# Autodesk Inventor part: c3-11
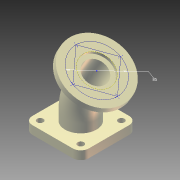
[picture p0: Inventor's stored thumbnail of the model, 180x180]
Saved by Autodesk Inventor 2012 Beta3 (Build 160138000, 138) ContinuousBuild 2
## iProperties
Created: 2010-11
Part Number: c3-11
Material: Cast Iron
Document SubType Name: Modeling
Designer: Beta-8540w
Density: 7.25 g/cm^3
Mass: 1087.5 g
Surface Area: 260 cm^2
Volume: 150 cm^3
Author: Beta-8540w
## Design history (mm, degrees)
sketch "Sketch1"
  geometry: L1 (-50, -50)-(50, -50); L2 (50, -50)-(50, 50); L3 (50, 50)-(-50, 50); L4 (-50, 50)-(-50, -50); C1 r 20 at (0, 0); C2 r 28 at (0, 0); 3 further points
  constraints: 8 end point, 3 perpendicular, 2 centre point, 2 coincident, 2 midpoint, 1 horizontal, 1 horizontal alignment, 1 parallel, 1 vertical alignment
  dimensions: "Width" = 100 distance of L1.start L1.end; "d6" = 40 diameter of C1; "d7" = 8 radial gap between concentric circles of C2 C1
extrude "Extrusion1" new body sketch "Sketch1" distance "d3" = 15; taper "d4" = 0 deg
fillet "Fillet1" dims "d5" = 14
sketch "Sketch2"
  geometry: L1 (0, 0)-(0, 30); L2 (-13.397, 80)-(-28.397, 105.981); A1 r 100 centre (-100, 30) between (0, 30) and (-13.397, 80)
  constraints: 4 end point, 2 point on circle, 2 tangent, 1 centre point, 1 vertical
  dimensions: "d8" = 30 distance of L1.start L1.end; "d9" = 100 radius of A1; "d10" = 30 distance of L2.start L2.end; "d11" = 30 deg angle of L2 L1
sketch "Sketch3"
  geometry: L1 (-13.397, 80)-(-28.397, 105.981) reference; L2 (-28.397, 105.981)-(-76.029, 78.481); L3 (-76.029, 78.481)-(-71.029, 69.821); L4 (-71.029, 69.821)-(-23.397, 97.321); L5 (-23.397, 97.321)-(-28.397, 105.981); 1 further point
  constraints: 8 end point, 2 parallel, 2 perpendicular
  dimensions: "d16" = 10 distance of L3.end L2.end; "d17" = 110 diameter of L3 L5
revolve "Revolution1" sketch "Sketch3" stored, may be unused: angle "d18" = 90 deg
sweep "Sweep1" dims "d19" = 0
sweep "Sweep2" dims "d20" = 0
sketch "Sketch4"
  geometry: C1 r 20 at (0, 0) reference; C2 r 55 at (0, 0) reference; C3 r 27.5 at (0, 0); 1 further point
  constraints: 1 centre point, 1 coincident
  dimensions: "d21" = 55 diameter of C3
extrude "Extrusion2" cut sketch "Sketch4" distance "d22" = 5; taper "d23" = 0 deg
sketch "Sketch5"
  geometry: L1 (0, 0)-(0, 9.711); L2 (-25, 0)-(-27, 0); L3 (-27, 0)-(-27, 1.5); L4 (-26.5, 2)-(-25.5, 2); L5 (-25, 1.5)-(-25, 0); A1 r 0.5 centre (-25.5, 1.5) between (-25, 1.5) and (-25.5, 2); A2 r 0.5 centre (-26.5, 1.5) between (-26.5, 2) and (-27, 1.5); 1 further point
  constraints: 10 end point, 4 point on circle, 4 tangent, 3 point on line, 2 centre point, 2 parallel, 1 equal radius, 1 horizontal, 1 perpendicular, 1 vertical
  dimensions: "d24" = 2 distance of L2.start L2.end; "d25" = 2 distance of point (-25, 2) L2.start; "d26" = 50 diameter of L5 L1; "d27" = 0.5 radius of A1
revolve "Revolution2" sketch "Sketch5" stored, may be unused: angle "d28" = 90 deg
hole "Hole1" diameter "d31" = 11; stored, may be unused: countersink angle "d35" = 7.5 deg, drill point angle "d37" = 118 deg; dims "d29" = 10, "d30" = 10, "d32" = 6, "d33" = 28, "d34" = 2, "d36" = 8
pattern_circular "Circular Pattern1" dims angle "d39" = 360 deg
sketch "Hole Sketch" dims "d41" = 85
  geometry: L1 (0, -42.5)-(-42.5, 0); L2 (-42.5, 0)-(0, 42.5); L3 (0, 42.5)-(42.5, 0); L4 (42.5, 0)-(0, -42.5); C1 r 27.5 at (0, 0) reference; 2 further points
  constraints: 8 end point, 2 coincident, 2 horizontal alignment, 11 other
body "Solid1"
